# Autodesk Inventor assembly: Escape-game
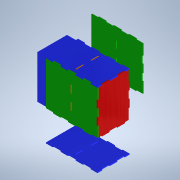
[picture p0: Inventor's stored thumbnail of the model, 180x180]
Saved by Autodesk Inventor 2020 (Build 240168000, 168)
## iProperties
Created: 2023-12
Part Number: Escape-game
Document SubType Name: Assembly
Designer: bruno
Author: bruno
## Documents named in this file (4)
- C:\Users\bruno\Documents\1-Cours-2023-24\1STI2D\IT\Escape-game\Inventor_uhl\Escape-game.iam
- C:\Users\bruno\Documents\1-Cours-2023-24\1STI2D\IT\Escape-game\Inventor_uhl\Boite\Ensemble1-boite2.iam
- C:\Users\bruno\Documents\1-Cours-2023-24\1STI2D\IT\Escape-game\Inventor_uhl\Boite\axe motoreducteur.ipt
- C:\Users\bruno\Documents\1-Cours-2023-24\1STI2D\IT\Escape-game\Inventor_uhl\Boite\Boite_amov_vis.iam
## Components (3 placed, 3 different names)
1. Ensemble1-boite2:1 [sub-assembly] — Logement:1, Placage:1, Placage:2
2. axe motoreducteur:1 — Logement:1
3. Boite_amov_vis:1 [sub-assembly] — Placage:1, Placage:2
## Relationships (3: Mate 2, Insert 1)
- Logement:1 [Insert]: Ensemble1-boite2:1 ↔ axe motoreducteur:1
- Placage:1 [Mate]: Ensemble1-boite2:1 ↔ Boite_amov_vis:1
- Placage:2 [Mate]: Ensemble1-boite2:1 ↔ Boite_amov_vis:1
